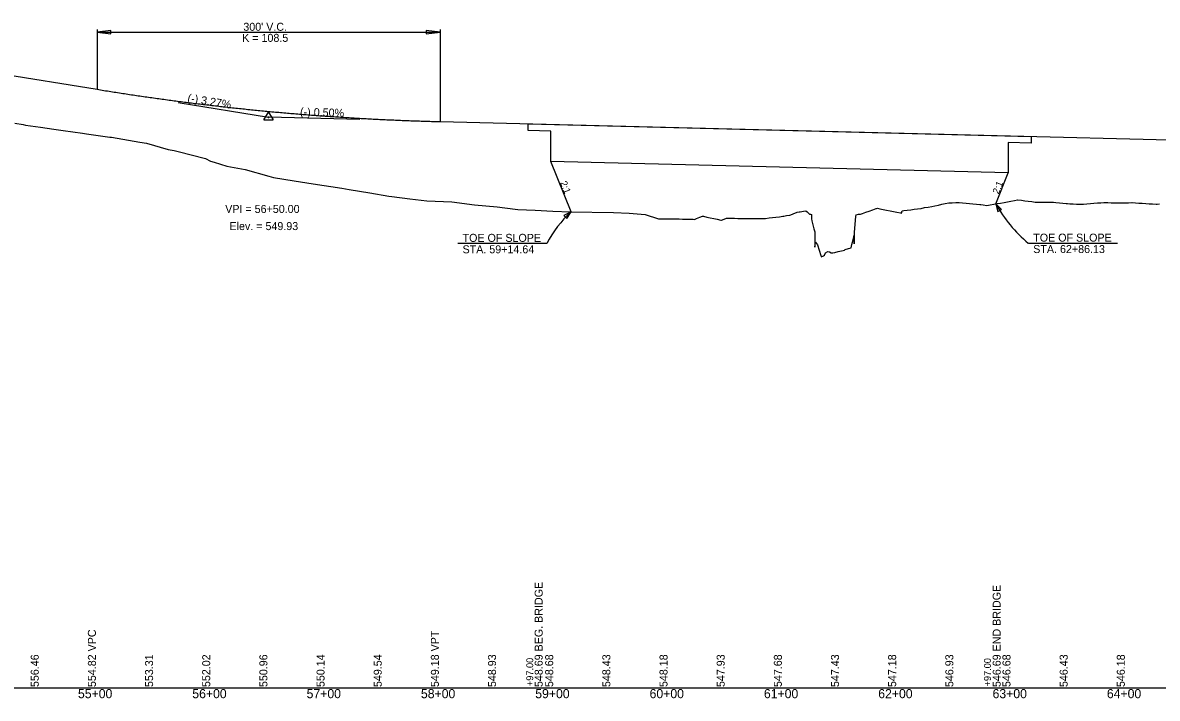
# Model space of a CAD drawing. Extents: x 49922 to 54713, y 49991 to 62800.
# Drawn here: x 51435 to 52427, y 61991 to 62582 of the extents above; entities that cross this region are included whole.
import ezdxf

# ---------------------------------------------------------------- set-up
doc = ezdxf.new("R2010")
doc.units = 0
for name, color, linetype in [('RD_DDB_GradeTX', 7, 'Continuous'), ('RD_DDB_Profile_EX', 7, 'Continuous'), ('RD_DDB_Profile_Lbl', 7, 'Continuous'), ('RD_DDB_Profile_PR', 7, 'Continuous'), ('RD_DDB_StaTX', 7, 'Continuous'), ('RD_DDB_StripGrade', 7, 'Continuous'), ('RD_DDB_VCLbl', 7, 'Continuous'), ('RD_GPK_Profile_Cell', 7, 'Continuous'), ('RD_Sketch8', 7, 'Continuous'), ('RD_TX_Profile', 7, 'Continuous')]:
    doc.layers.add(name, color=color, linetype=linetype)

msp = doc.modelspace()

# ---------------------------------------------------------------- linework, layer by layer
at = {"layer": 'RD_DDB_GradeTX'}
for p, q in [((51571.05, 62512.52), (51650, 62499.63)), ((51646.03, 62497.33), (51650, 62504.21)), ((51646.03, 62497.33), (51653.97, 62497.33)), ((51650, 62504.21), (51653.97, 62497.33)), ((51729.98, 62497.63), (51650, 62499.63))]:
    msp.add_line(p, q, dxfattribs=at)
msp.add_circle((51650, 62499.63), 0.529, dxfattribs=at)
at = {"layer": 'RD_DDB_Profile_EX'}
for points in [[(51427.99, 62494.54), (51435.23, 62493.2), (51437.32, 62492.79), (51450.56, 62490.86), (51462.34, 62489.21), (51470.25, 62488.07), (51487.36, 62485.68), (51490.89, 62485.17), (51511.3, 62482.34), (51512.51, 62482.13), (51537.48, 62477.82), (51543.2, 62476.83), (51562.19, 62471.51), (51567.43, 62470.45), (51570.88, 62469.79)], [(51570.88, 62469.79), (51594.78, 62463.42), (51599.27, 62461.24), (51602.35, 62460.38), (51613.58, 62456.83), (51629.53, 62453.91), (51650.31, 62448.02), (51654.32, 62446.88), (51672.38, 62443.96), (51689.02, 62441.27), (51714.08, 62437.71), (51720.41, 62436.27), (51738.49, 62433.36), (51755.25, 62430.65), (51757.87, 62430.23), (51773.48, 62428.27), (51788.4, 62426.39), (51810.3, 62425.47), (51830.27, 62423.04), (51849.92, 62421.09), (51865.77, 62419.18), (51868.1, 62418.89), (51883.36, 62418.22), (51898.72, 62417.54), (51914.19, 62416.86), (51951.79, 62416.16), (51965.37, 62415.56), (51979.31, 62414.47), (51990.97, 62410.69), (52006.06, 62410.65), (52009.22, 62410.58), (52012.24, 62410.51), (52015.26, 62410.44), (52018.29, 62410.37), (52021.31, 62410.29), (52022.59, 62410.26), (52024.33, 62410.96), (52027.36, 62412.17), (52029.64, 62413.09), (52030.38, 62412.93), (52033.4, 62412.28), (52036.42, 62411.63), (52039.45, 62410.97), (52042.47, 62410.32), (52045.49, 62409.66), (52046.33, 62409.48), (52048.52, 62410.42), (52050.46, 62411.25), (52051.54, 62411.24), (52054.56, 62411.2), (52057.58, 62411.17), (52060.61, 62411.13), (52063.63, 62411.09), (52066.91, 62411.06), (52069.68, 62411.03), (52072.7, 62411), (52075.72, 62410.97), (52078.33, 62410.95), (52078.75, 62410.94), (52081.77, 62410.89), (52083.04, 62410.87), (52084.79, 62411.09), (52087.81, 62411.47), (52090.84, 62411.85), (52093.86, 62412.23), (52096.88, 62412.61), (52099.91, 62412.99), (52100.84, 62413.11), (52102.93, 62413.5), (52105.95, 62414.06), (52106.99, 62414.25), (52108.97, 62415.07), (52112.26, 62416.42), (52114.16, 62416.7), (52115.02, 62416.85), (52118.04, 62417.39), (52119.88, 62417.72), (52121.07, 62416.71), (52123.31, 62414.8), (52124.09, 62414.72), (52124.98, 62414.63), (52125.02, 62410.68), (52125.21, 62409), (52127.11, 62401.91), (52127.78, 62399.42), (52127.98, 62385.85), (52128.49, 62390.32), (52130.13, 62387.86), (52133.16, 62378.7), (52133.53, 62377.57), (52135.38, 62378.3), (52136.32, 62378.99), (52137.17, 62381.03), (52139.2, 62382.01), (52140.66, 62381.68), (52142.23, 62381.04), (52143.53, 62380.95), (52145.25, 62381.33), (52148.27, 62382.01), (52151.3, 62382.68), (52152.68, 62382.99)], [(52152.68, 62382.99), (52153.73, 62383.22), (52154.44, 62383.77), (52157.34, 62384.68), (52159.62, 62385.38), (52160.36, 62388.17), (52161.79, 62393.53), (52162.3, 62396.38), (52162.33, 62388.86), (52162.58, 62399.06), (52163.68, 62412.89), (52164.1, 62414.1), (52166.03, 62414.86), (52166.41, 62414.83), (52167.74, 62414.73), (52169.43, 62415.34), (52172.46, 62416.43), (52175.48, 62417.52), (52178.5, 62418.61), (52181.52, 62419.69), (52181.88, 62419.82), (52182.77, 62420.06), (52184.76, 62419.55), (52187.57, 62419), (52190.59, 62418.41), (52193.62, 62417.81), (52196.64, 62417.21), (52199.66, 62416.6), (52202.68, 62415.99), (52203.78, 62415.77), (52204.38, 62417.85), (52205.71, 62418.01), (52208.73, 62418.37), (52211.75, 62418.74), (52214.78, 62419.1), (52217.8, 62419.46), (52220.82, 62419.82), (52223.84, 62420.52), (52226.87, 62421.02), (52230.08, 62421.56), (52232.91, 62422.17), (52235.94, 62422.82), (52238.96, 62423.47), (52241.98, 62424.11), (52245.11, 62424.78), (52248.03, 62424.87), (52251.05, 62424.97), (52253.57, 62425.06), (52254.07, 62425.01), (52257.1, 62424.74), (52260.12, 62424.47), (52263.14, 62424.2), (52266.17, 62423.93), (52269.19, 62423.65), (52272.21, 62423.37), (52273.14, 62423.28), (52275.23, 62422.89), (52278.26, 62422.32), (52281.28, 62422.88), (52284.3, 62423.44), (52287.33, 62424.01), (52290.35, 62424.57), (52293.37, 62425.14), (52296.39, 62425.71), (52299.42, 62426.29), (52302.44, 62426.86), (52305.11, 62427.37), (52305.46, 62427.33), (52308.49, 62426.95), (52311.51, 62426.57), (52314.53, 62426.2), (52317.55, 62425.82), (52320.58, 62425.45), (52321.65, 62425.32), (52323.6, 62425.3), (52326.62, 62425.28), (52329.65, 62425.26), (52332.67, 62425.25), (52335.69, 62425.23), (52336.76, 62425.22), (52338.72, 62425.03), (52341.74, 62424.73), (52344.76, 62424.42), (52347.78, 62424.12), (52348.79, 62424.02), (52350.81, 62423.94), (52353.83, 62423.82), (52356.85, 62423.7), (52359.88, 62423.57), (52360.96, 62423.53), (52362.9, 62423.68), (52365.92, 62423.9), (52368.94, 62424.13), (52371.97, 62424.35), (52374.99, 62424.58), (52378.01, 62424.8), (52380.54, 62424.99), (52381.04, 62424.98), (52384.06, 62424.91), (52387.08, 62424.83), (52390.1, 62424.75)], [(52390.1, 62424.75), (52393.3, 62424.67), (52396.15, 62424.73), (52399.17, 62424.79), (52402.2, 62424.84), (52405.22, 62424.9), (52405.52, 62424.91), (52408.24, 62424.72), (52411.26, 62424.52), (52414.29, 62424.32), (52417.31, 62424.11), (52420.33, 62423.91), (52423.36, 62423.71), (52426.38, 62423.5), (52427.29, 62423.44), (52429.4, 62423.77)]]:
    msp.add_lwpolyline(points, dxfattribs=at)
at = {"layer": 'RD_DDB_Profile_PR'}
for p, q in [((51350, 62548.61), (51500, 62524.12)), ((51800, 62495.88), (53000, 62465.88))]:
    msp.add_line(p, q, dxfattribs=at)
msp.add_spline([(51500, 62524.12), (51506, 62523.14), (51512, 62522.19), (51518, 62521.25), (51524, 62520.33), (51530, 62519.43), (51536, 62518.54), (51542, 62517.66), (51548, 62516.81), (51554, 62515.97), (51560, 62515.15), (51566, 62514.34), (51572, 62513.55), (51578, 62512.78), (51584, 62512.03), (51590, 62511.29), (51596, 62510.57), (51602, 62509.86), (51608, 62509.17), (51614, 62508.5), (51620, 62507.84), (51626, 62507.2), (51632, 62506.58), (51638, 62505.97), (51644, 62505.38), (51650, 62504.81), (51656, 62504.25), (51662, 62503.71), (51668, 62503.19), (51674, 62502.68), (51680, 62502.19), (51686, 62501.72), (51692, 62501.26), (51698, 62500.82), (51704, 62500.4), (51710, 62499.99), (51716, 62499.6), (51722, 62499.23), (51728, 62498.87), (51734, 62498.53), (51740, 62498.2), (51746, 62497.9), (51752, 62497.61), (51758, 62497.33), (51764, 62497.07), (51770, 62496.83), (51776, 62496.61), (51782, 62496.4), (51788, 62496.21), (51794, 62496.03), (51800, 62495.88)], degree=3, dxfattribs=at)
at = {"layer": 'RD_DDB_VCLbl'}
for p, q in [((51500, 62576.62), (51500, 62524.12)), ((51512, 62575.62), (51500, 62574.12)), ((51512, 62572.62), (51512, 62575.62)), ((51800, 62574.12), (51788, 62575.62)), ((51788, 62575.62), (51788, 62572.62)), ((51800, 62576.62), (51800, 62495.88)), ((51500, 62574.12), (51800, 62574.12)), ((51500, 62574.12), (51512, 62572.62)), ((51788, 62572.62), (51800, 62574.12))]:
    msp.add_line(p, q, dxfattribs=at)
at = {"layer": 'RD_GPK_Profile_Cell'}
msp.add_line((50000, 62000), (54700, 62000), dxfattribs=at)
at = {"layer": 'RD_Sketch8'}
for p, q in [((51877, 62493.95), (52317, 62482.95)), ((51877, 62488.1), (51877, 62493.95)), ((51897, 62487.6), (51877, 62488.1)), ((51897, 62460.95), (51897, 62487.6)), ((52317, 62477.1), (52297, 62477.6)), ((52297, 62477.6), (52297, 62450.95)), ((52317, 62482.95), (52317, 62477.1)), ((52297, 62450.95), (51897, 62460.95)), ((51914.64, 62416.85), (51897, 62460.95)), ((52286.13, 62423.78), (52297, 62450.95))]:
    msp.add_line(p, q, dxfattribs=at)
at = {"layer": 'RD_TX_Profile'}
for p, q in [((51893.4, 62389.05), (51815.47, 62389.05)), ((52392.57, 62389.25), (52314.64, 62389.25))]:
    msp.add_line(p, q, dxfattribs=at)
for points in [[(51910.89, 62410.94), (51914.64, 62416.85), (51908.44, 62413.61)], [(52291.01, 62418.77), (52286.13, 62423.78), (52287.85, 62417)]]:
    msp.add_lwpolyline(points, close=True, dxfattribs=at)
for centre, radius, start, end in [((51982.86, 62342.69), 100.77, 132.61402, 152.60727), ((52394.67, 62484.43), 124.33, 209.19749, 229.81394)]:
    msp.add_arc(centre, radius, start, end, dxfattribs=at)

# ---------------------------------------------------------------- texts
at = {"layer": 'RD_DDB_GradeTX'}
for s, rotation, p in [('(-) 3.27%', 350.72699, (51578.75, 62513.29)), ('(-) 0.50%', 358.56791, (51677.52, 62500.94))]:
    msp.add_text(s, height=7, rotation=rotation, dxfattribs=at).set_placement(p)
at = {"layer": 'RD_DDB_Profile_Lbl'}
for s, p in [('VPI = 56+50.00', (51612.11, 62415.87)), ('Elev. = 549.93', (51615.84, 62400.87))]:
    msp.add_text(s, height=7, dxfattribs=at).set_placement(p)
at = {"layer": 'RD_DDB_StaTX'}
for s, p in [('55+00', (51483.32, 61991)), ('56+00', (51583.32, 61991)), ('57+00', (51683.32, 61991)), ('58+00', (51783.32, 61991)), ('59+00', (51883.32, 61991)), ('60+00', (51983.32, 61991)), ('61+00', (52083.32, 61991)), ('62+00', (52183.32, 61991)), ('63+00', (52283.32, 61991)), ('64+00', (52383.32, 61991))]:
    msp.add_text(s, height=8, dxfattribs=at).set_placement(p)
at = {"layer": 'RD_DDB_StripGrade'}
for s, p in [('548.69 BEG. BRIDGE', (51889.78, 62000.75)), ('546.69 END BRIDGE', (52290.41, 62000.75)), ('554.82 VPC', (51499, 62000.75)), ('549.18 VPT', (51799, 62000.75)), ('550.14', (51699, 62000.75)), ('549.54', (51749, 62000.75)), ('556.46', (51449, 62000.75)), ('554.82', (51499, 62000.75)), ('553.31', (51549, 62000.75)), ('552.02', (51599, 62000.75)), ('550.96', (51649, 62000.75)), ('549.18', (51799, 62000.75)), ('548.93', (51849, 62000.75)), ('548.68', (51899, 62000.75)), ('548.43', (51949, 62000.75)), ('548.18', (51999, 62000.75)), ('547.93', (52049, 62000.75)), ('547.68', (52099, 62000.75)), ('547.43', (52149, 62000.75)), ('547.18', (52199, 62000.75)), ('546.93', (52249, 62000.75)), ('546.68', (52299, 62000.75)), ('546.43', (52349, 62000.75)), ('546.18', (52399, 62000.75))]:
    msp.add_text(s, height=7, rotation=90, dxfattribs=at).set_placement(p)
at = {"layer": 'RD_DDB_VCLbl'}
for s, p in [("300' V.C.", (51627.96, 62575.37)), ('K = 108.5', (51626.94, 62565.68))]:
    msp.add_text(s, height=7, dxfattribs=at).set_placement(p)
at = {"layer": 'RD_TX_Profile'}
for s, rotation, p in [('2:1', 291.80141, (51905, 62442.45)), ('2:1', 68.19859, (52288.57, 62431.92)), ('+97.00', 90, (51881.52, 62001.61)), ('+97.00', 90, (52281.88, 62001.32))]:
    msp.add_text(s, height=6, rotation=rotation, dxfattribs=at).set_placement(p)
for s, p in [('TOE OF SLOPE', (51819.72, 62390.55)), ('TOE OF SLOPE', (52318.89, 62390.75)), ('STA. 59+14.64', (51819.72, 62380.55)), ('STA. 62+86.13', (52318.89, 62380.75))]:
    msp.add_text(s, height=7, dxfattribs=at).set_placement(p)

doc.saveas('drawing.dxf')
